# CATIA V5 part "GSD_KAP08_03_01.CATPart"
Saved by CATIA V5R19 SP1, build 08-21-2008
Part number: GSD_ANALYSIS_02
Description: Beispielmodell für Auszugsschrägenanalyse.  Maik Hertha IT Consultants
Bounding box of the stored display mesh (mm): x -107.737 to 0, y -127.079 to 435.495, z -8.778 to 167.189
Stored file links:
  \GSD_BUCH_UEBUNG\GSD_KAP08_03_01.CATPart
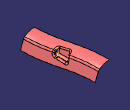
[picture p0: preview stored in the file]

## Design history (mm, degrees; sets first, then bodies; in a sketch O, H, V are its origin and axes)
AxisSystem1 "Absolute Axis System": origin (0, 0, 0), X (1, 0, 0), Y (0, 1, 0), Z (0, 0, 1)
Set1
  Sketch1 on YZ plane of AxisSystem1, origin (0, 0, 0), H (0, 1, 0), V (0, 0, 1)
    spline S1 through (-119.326, 61.6479) (67.9562, 81.1703) (238.2652, 113.8148) (431.576, 131.4141)
    construction line L1 (-119.326, 61.6479) -> (-218.4639, 61.6479)
    point P1 (-119.326, 61.6479)
    construction line L2 (431.576, 131.4141) -> (489.6444, 131.4141)
    point P3 (431.576, 131.4141)
    point P6 (431.576, 131.4141)
    point P7 (-119.326, 61.6479)
    horizontal: L1 H, L2 H
    coincidence: P6 P3, P7 P1
Set2 "Fillets.1"
  Plane1: type Equation, A -0.425234, B -0.0139709, C 0.904976, RefAxis AxisSystem1, Length 86.6628
  Point1: type OnCurve, Support Sketch1, Ratio 0.5
  Line1: type Normal, RefSkin Plane1, Start 0, End 50, RefPoint Point1
  DatumSurface1 "X-Fillet.6"
Body1 (main body)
